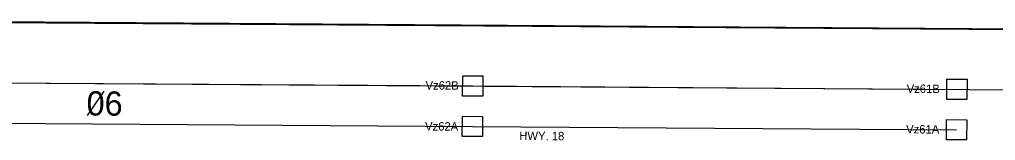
# Model space of a CAD drawing. Extents: x 1802372 to 1804337, y 572813 to 574117.
# Drawn here: x 1803675.5 to 1803965.8, y 573817.4 to 573853.2 of the extents above; entities that cross this region are included whole.
import ezdxf

# ---------------------------------------------------------------- set-up
doc = ezdxf.new("R2010")
doc.units = 0
for name, color, linetype in [('DSN_DRFT_Common-Annotations', 7, 'Continuous'), ('DSN_DRFT_DNC', 7, 'Continuous'), ('DSN_TRAF_Permanent Signal', 7, 'Continuous'), ('DSN_TRAF_Permanent Signal Notes', 7, 'Continuous'), ('S_PRIMARY_CTL', 7, 'Continuous')]:
    doc.layers.add(name, color=color, linetype=linetype)

msp = doc.modelspace()

# ---------------------------------------------------------------- linework, layer by layer
at = {"layer": 'DSN_DRFT_Common-Annotations'}
msp.add_line((1803700.55, 573831.97), (1803695.65, 573824.73), dxfattribs=at)
at = {"layer": 'DSN_DRFT_DNC'}
for p, q in [((1803580.64, 573853.09), (1804318.42, 573847.97)), ((1803568.31, 573835.18), (1804318.29, 573829.97)), ((1803665.31, 573834.51), (1803810.31, 573833.5)), ((1803810.31, 573833.5), (1803954.3, 573832.5)), ((1803665.23, 573822.51), (1803810.22, 573821.5)), ((1803810.22, 573821.5), (1803954.22, 573820.5))]:
    msp.add_line(p, q, dxfattribs=at)
at = {"layer": 'DSN_TRAF_Permanent Signal'}
for points in [[(1803807.28, 573830.52), (1803807.33, 573836.52), (1803813.33, 573836.48), (1803813.28, 573830.48)], [(1803951.28, 573829.52), (1803951.32, 573835.52), (1803957.32, 573835.48), (1803957.28, 573829.48)], [(1803807.2, 573818.52), (1803807.24, 573824.52), (1803813.24, 573824.48), (1803813.2, 573818.48)], [(1803951.2, 573817.52), (1803951.24, 573823.52), (1803957.24, 573823.48), (1803957.2, 573817.48)]]:
    msp.add_lwpolyline(points, close=True, dxfattribs=at)
at = {"layer": 'S_PRIMARY_CTL'}
for p, q in [((1803582.51, 573853.21), (1804316.54, 573848.11)), ((1803582.51, 573852.96), (1804316.54, 573847.86))]:
    msp.add_line(p, q, dxfattribs=at)

# ---------------------------------------------------------------- texts
at = {"layer": 'DSN_DRFT_Common-Annotations'}
for s, height, p in [('Vz62B', 2.5, (1803796.26, 573832.46)), ('Vz61B', 2.5, (1803939.36, 573831.47)), ('06', 7.2, (1803695.43, 573824.75)), ('Vz62A', 2.5, (1803796.11, 573820.31)), ('Vz61A', 2.5, (1803939.2, 573819.44))]:
    msp.add_text(s, height=height, rotation=359.6021, dxfattribs=at).set_placement(p)
at = {"layer": 'DSN_TRAF_Permanent Signal Notes'}
msp.add_text('HWY. 18', height=2.5, rotation=359.6021, dxfattribs=at).set_placement((1803824.14, 573817.48))

doc.saveas('drawing.dxf')
